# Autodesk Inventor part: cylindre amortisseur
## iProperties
Created: 2011-01
Part Number: cylindre amortisseur
Document SubType Name: Modeling
Designer: eric
Density: 1 g/cm^3
Mass: 0.327629 g
Surface Area: 5.2906 cm^2
Volume: 0.327629 cm^3
Author: eric
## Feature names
1. Base1
